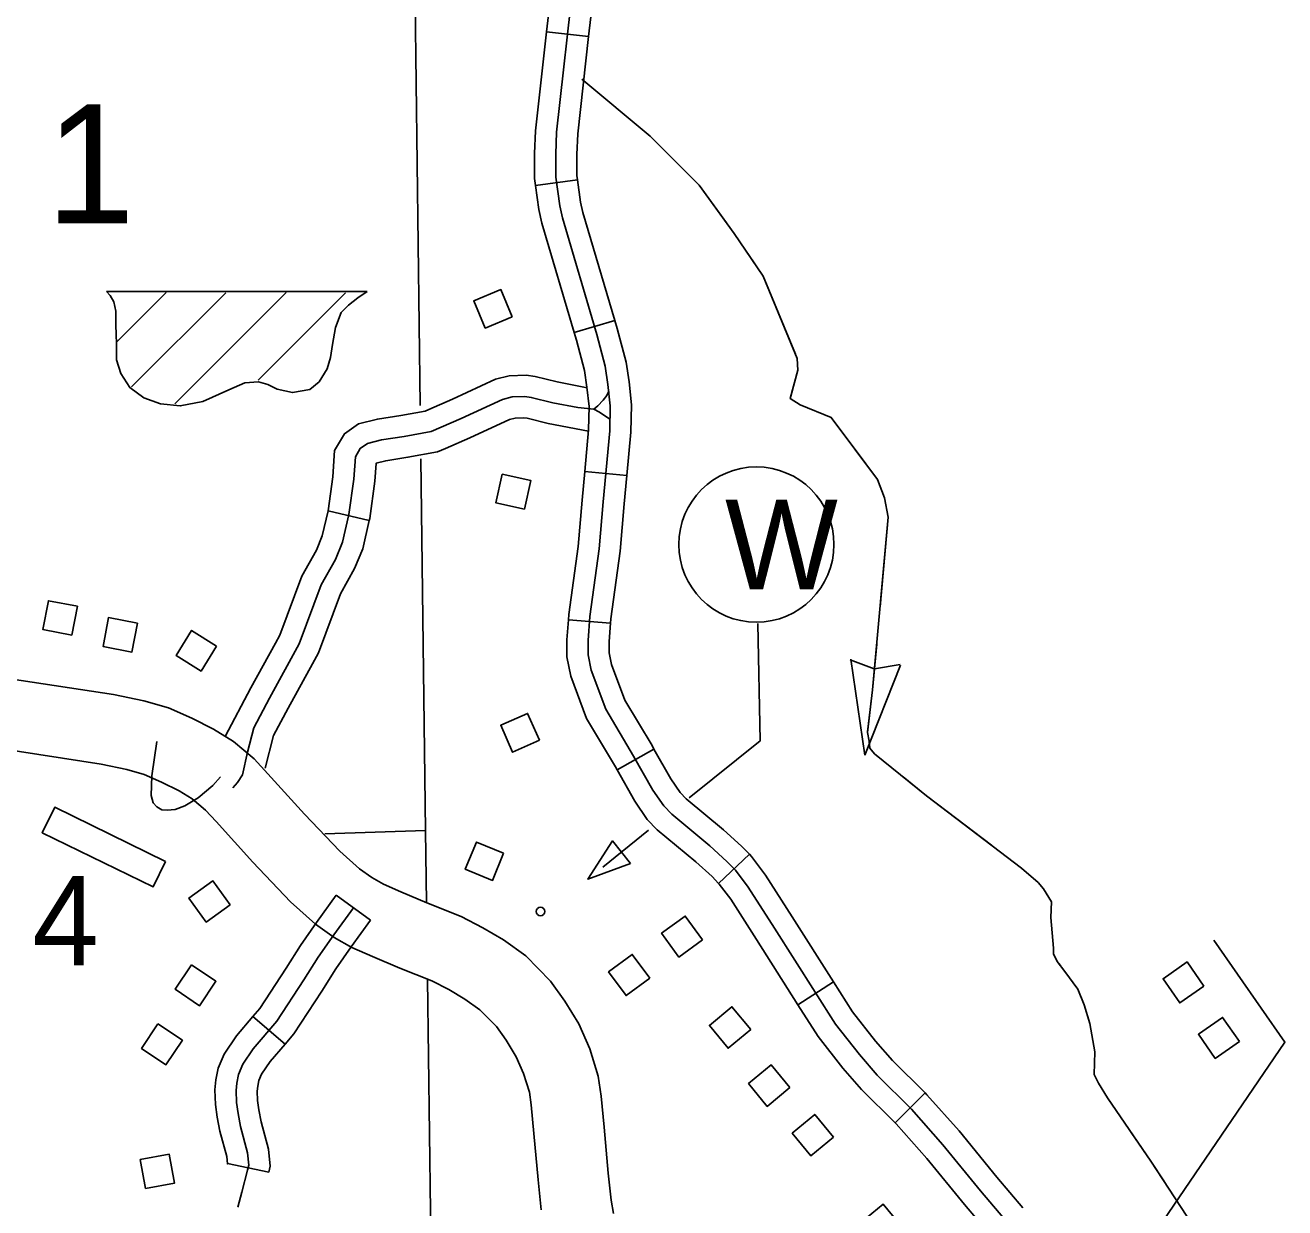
# Model space of a CAD drawing. Extents: x 155 to 3386, y 68 to 2138.
# Drawn here: x 2032.7 to 2160.3, y 1017.8 to 1137.5 of the extents above; entities that cross this region are included whole.
import ezdxf

# ---------------------------------------------------------------- set-up
doc = ezdxf.new("R2010")
doc.units = 0
for name, color, linetype in [('Level 10', 7, 'Continuous'), ('Level 32', 7, 'Continuous'), ('Level 43', 7, 'Continuous'), ('Level 45', 7, 'Continuous'), ('Level 5', 7, 'Continuous'), ('Level 56', 7, 'Continuous'), ('Level 57', 7, 'Continuous')]:
    doc.layers.add(name, color=color, linetype=linetype)

msp = doc.modelspace()

# ---------------------------------------------------------------- linework, layer by layer
at = {"layer": 'Level 10'}
for points in [[(2092.33, 1017.22), (2092.09, 1018.57), (2091.8, 1021.3), (2091.38, 1025.93), (2091.09, 1029.09), (2090.78, 1031.1), (2089.92, 1033.88), (2088.82, 1036.39), (2087.41, 1038.69), (2085.96, 1040.73), (2083.44, 1043.29), (2081.17, 1044.9), (2079.09, 1046.12), (2076.9, 1047.26), (2073.43, 1048.64), (2070.78, 1049.78), (2069.03, 1050.56), (2067.85, 1051.21), (2066.59, 1052.1), (2064.6, 1053.88), (2061.04, 1057.65), (2057.33, 1061.72), (2055.92, 1063.24), (2053.85, 1064.98), (2051.82, 1066.23), (2049.62, 1067.34), (2047.24, 1068.4), (2044.74, 1069.11), (2041.69, 1069.74), (2031.2, 1071.34)], [(2030.21, 1064.27), (2040.43, 1062.7), (2043.04, 1062.17), (2044.8, 1061.66), (2046.56, 1060.89), (2048.32, 1059.99), (2049.65, 1059.17), (2050.99, 1058.05), (2052.08, 1056.88), (2055.8, 1052.79), (2059.61, 1048.75), (2062.13, 1046.51), (2064.04, 1045.15), (2065.84, 1044.15), (2067.93, 1043.23), (2070.7, 1042.04), (2073.93, 1040.75), (2075.64, 1039.87), (2077.28, 1038.9), (2078.79, 1037.83), (2080.47, 1036.12), (2081.45, 1034.74), (2082.48, 1033.08), (2083.21, 1031.39), (2083.81, 1029.48), (2084, 1028.22), (2084.27, 1025.29), (2084.69, 1020.6), (2085.01, 1017.58)]]:
    msp.add_lwpolyline(points, dxfattribs=at)
at = {"layer": 'Level 32'}
for p, q in [((2085.55, 1136.83), (2089.81, 1136.36)), ((2084.43, 1121.28), (2088.68, 1121.87)), ((2088.36, 1106.41), (2092.47, 1107.63)), ((2089.41, 1092.33), (2093.68, 1091.93)), ((2087.76, 1077.3), (2092.03, 1076.98)), ((2092.69, 1062.12), (2096.42, 1064.23)), ((2102.98, 1050.62), (2106.09, 1053.57)), ((2064.25, 1049.42), (2067.71, 1046.89)), ((2111.01, 1038.34), (2114.62, 1040.65)), ((2055.81, 1037.14), (2059.06, 1034.35)), ((2120.87, 1026.37), (2123.89, 1029.42)), ((2053.22, 1022.25), (2057.42, 1021.39))]:
    msp.add_line(p, q, dxfattribs=at)
for points in [[(2087.62, 1151.32), (2087.24, 1149.53), (2086.24, 1142.92), (2085.55, 1136.83)], [(2091.95, 1151.07), (2091.46, 1148.77), (2090.49, 1142.36), (2089.81, 1136.36)], [(2088.36, 1142.64), (2086.57, 1126.67), (2086.48, 1124.47), (2086.48, 1122.14), (2086.88, 1119.22), (2087.15, 1118.01), (2090.65, 1106.21), (2091.5, 1102.98), (2091.77, 1101.14), (2092, 1098.98), (2091.95, 1096.43), (2091.28, 1089.25), (2090.87, 1084.49), (2089.93, 1077.63), (2089.75, 1075.2), (2089.75, 1073.77), (2090.07, 1072.2), (2091.55, 1068.25), (2094.37, 1063.49), (2096.3, 1060.08), (2097.42, 1058.47), (2098.23, 1057.62), (2102.07, 1054.42), (2103.82, 1052.85), (2104.67, 1051.95), (2105.97, 1050.25), (2108.62, 1046.08), (2114.8, 1036.38), (2117.23, 1033.29), (2119.02, 1031.22), (2122.52, 1027.76), (2125.7, 1024.17), (2129.51, 1019.5), (2134.22, 1013.94)], [(2085.55, 1136.83), (2084.43, 1126.83), (2084.34, 1124.51), (2084.34, 1121.99), (2084.43, 1121.28)], [(2089.81, 1136.36), (2088.71, 1126.5), (2088.62, 1124.43), (2088.62, 1122.28), (2088.68, 1121.87)], [(2088.68, 1121.87), (2088.99, 1119.6), (2089.23, 1118.55), (2092.47, 1107.63)], [(2084.43, 1121.28), (2084.77, 1118.84), (2085.08, 1117.47), (2088.36, 1106.41)], [(2092.47, 1107.63), (2092.71, 1106.79), (2093.61, 1103.41), (2093.9, 1101.4), (2094.14, 1099.08), (2094.09, 1096.31), (2093.68, 1091.93)], [(2088.36, 1106.41), (2088.59, 1105.63), (2089.4, 1102.55), (2089.64, 1100.87), (2089.85, 1098.89), (2089.81, 1096.55), (2089.41, 1092.33)], [(2089.41, 1092.33), (2089.14, 1089.44), (2088.74, 1084.73), (2087.8, 1077.85), (2087.76, 1077.3)], [(2093.68, 1091.93), (2093.41, 1089.06), (2093.01, 1084.26), (2092.06, 1077.4), (2092.03, 1076.98)], [(2087.76, 1077.3), (2087.61, 1075.28), (2087.61, 1073.56), (2088, 1071.61), (2089.61, 1067.32), (2092.52, 1062.42), (2092.69, 1062.12)], [(2092.03, 1076.98), (2091.9, 1075.13), (2091.9, 1073.98), (2092.13, 1072.79), (2093.49, 1069.18), (2096.23, 1064.57), (2096.42, 1064.23)], [(2046.08, 1065), (2045.56, 1061.53), (2045.49, 1059.53), (2045.7, 1058.79), (2046.06, 1058.36), (2046.59, 1058.07), (2047.12, 1058.04), (2047.94, 1058.11), (2048.9, 1058.47), (2050.26, 1059.28), (2051.75, 1060.53), (2052.53, 1061.42)], [(2096.42, 1064.23), (2098.12, 1061.22), (2099.09, 1059.82), (2099.7, 1059.18), (2103.47, 1056.04), (2105.31, 1054.39), (2106.09, 1053.57)], [(2092.69, 1062.12), (2094.48, 1058.94), (2095.75, 1057.11), (2096.76, 1056.05), (2100.67, 1052.8), (2102.32, 1051.31), (2102.98, 1050.62)], [(2106.09, 1053.57), (2106.3, 1053.35), (2107.73, 1051.47), (2110.42, 1047.23), (2114.62, 1040.65)], [(2102.98, 1050.62), (2103.04, 1050.56), (2104.21, 1049.02), (2106.81, 1044.93), (2111.01, 1038.34)], [(2064.25, 1049.42), (2062.24, 1046.67), (2060.64, 1044.33), (2059.17, 1042.03), (2056.51, 1037.96), (2055.81, 1037.14)], [(2065.98, 1048.16), (2063.99, 1045.43), (2062.43, 1043.15), (2060.97, 1040.87), (2058.23, 1036.67), (2055.84, 1033.89), (2054.77, 1032.33), (2054.35, 1031.29), (2054.17, 1030.4), (2054.1, 1029.65), (2054.13, 1028.44), (2054.31, 1027.34), (2054.56, 1026.02), (2055.27, 1023.35), (2055.38, 1022.11), (2055.27, 1021.59), (2054.67, 1019.38), (2054.28, 1017.85)], [(2067.71, 1046.89), (2065.74, 1044.19), (2064.21, 1041.97), (2062.77, 1039.71), (2059.94, 1035.38), (2059.06, 1034.35)], [(2114.62, 1040.65), (2116.55, 1037.62), (2118.88, 1034.65), (2120.58, 1032.69), (2123.89, 1029.42)], [(2111.01, 1038.34), (2113.05, 1035.14), (2115.57, 1031.92), (2117.45, 1029.76), (2120.87, 1026.37)], [(2055.81, 1037.14), (2054.14, 1035.2), (2052.88, 1033.35), (2052.29, 1031.92), (2052.05, 1030.72), (2051.95, 1029.73), (2052, 1028.24), (2052.2, 1026.97), (2052.47, 1025.55), (2053.15, 1022.98), (2053.22, 1022.23), (2053.22, 1022.25)], [(2059.06, 1034.35), (2057.55, 1032.59), (2056.67, 1031.3), (2056.41, 1030.67), (2056.29, 1030.09), (2056.24, 1029.58), (2056.27, 1028.65), (2056.42, 1027.71), (2056.65, 1026.5), (2057.39, 1023.72), (2057.54, 1021.98), (2057.42, 1021.39)], [(2123.89, 1029.42), (2124.07, 1029.23), (2127.33, 1025.56), (2131.16, 1020.87), (2133.78, 1017.78)], [(2120.87, 1026.37), (2120.96, 1026.28), (2124.07, 1022.78), (2127.87, 1018.13), (2130.5, 1015.01)]]:
    msp.add_lwpolyline(points, dxfattribs=at)
at = {"layer": 'Level 43'}
for p, q in [((2116.29, 1073.25), (2118.74, 1072.35)), ((2117.79, 1063.61), (2116.37, 1073.31)), ((2117.79, 1063.61), (2121.41, 1072.72)), ((2121.35, 1072.79), (2118.78, 1072.35))]:
    msp.add_line(p, q, dxfattribs=at)
for points in [[(2089.13, 1132.04), (2096.03, 1126.28), (2101, 1121.32), (2104.54, 1116.42), (2107.49, 1112.1), (2110.94, 1103.75), (2111.01, 1102.6), (2110.22, 1099.72), (2111.23, 1099.08), (2114.39, 1097.78), (2119.07, 1091.52), (2119.79, 1089.65), (2120.15, 1087.7), (2118.56, 1070.21), (2118.06, 1065.89), (2118.21, 1065.03), (2118.28, 1064.31), (2118.78, 1063.73), (2124.03, 1059.49), (2133.67, 1052.15), (2135.33, 1050.71), (2135.9, 1050.06), (2136.69, 1048.76), (2136.62, 1047.18), (2136.91, 1044.08), (2136.91, 1043.51), (2137.27, 1042.72), (2138.06, 1041.71), (2139.36, 1039.91), (2140, 1038.33), (2140.58, 1036.45), (2141.08, 1033.57), (2141.01, 1031.27), (2141.44, 1030.41), (2142.38, 1028.9), (2146.77, 1022.49), (2150.4, 1016.95)], [(2096.34, 1125.97), (2101, 1121.32), (2103.77, 1117.49)], [(2105.92, 1114.39), (2107.49, 1112.1), (2110.75, 1104.21)], [(2110.45, 1100.55), (2110.22, 1099.72), (2111.23, 1099.08), (2114.39, 1097.78), (2117.88, 1093.1)], [(2119.71, 1089.84), (2119.79, 1089.65), (2120.15, 1087.7), (2119.33, 1078.61)], [(2118.99, 1074.86), (2118.56, 1070.21), (2118.07, 1065.96)], [(2121.66, 1061.4), (2124.03, 1059.49), (2126.11, 1057.91)], [(2126.11, 1057.91), (2130.61, 1054.48)], [(2133.61, 1052.19), (2133.67, 1052.15), (2135.33, 1050.71), (2135.9, 1050.06), (2136.69, 1048.76), (2136.62, 1047.18), (2136.91, 1044.08), (2136.91, 1043.51), (2137.27, 1042.72), (2137.59, 1042.31)], [(2139.66, 1039.18), (2140, 1038.33), (2140.58, 1036.45), (2141.08, 1033.57), (2141.01, 1031.27), (2141.44, 1030.41), (2142.38, 1028.9), (2142.64, 1028.51)], [(2144.77, 1025.4), (2146.77, 1022.49), (2148.13, 1020.42)]]:
    msp.add_lwpolyline(points, dxfattribs=at)
at = {"layer": 'Level 45'}
msp.add_line((2067.59, 1087.37), (2063.42, 1088.34), dxfattribs=at)
for points in [[(2073.61, 1098.61), (2076.02, 1099.64), (2080.36, 1101.66), (2081.77, 1102), (2083.47, 1102.07), (2084.4, 1101.94), (2086.63, 1101.39), (2089.65, 1100.81)], [(2053.77, 1060.3), (2054.23, 1060.83), (2054.74, 1061.62), (2055.24, 1063.92), (2055.89, 1066.37), (2057.47, 1069.39), (2060.49, 1074.87), (2062.72, 1080.84), (2064.16, 1083.43), (2064.88, 1085.16), (2065.53, 1087.97), (2066.03, 1091.56), (2066.18, 1093.8), (2066.68, 1094.66), (2067.4, 1095.16), (2068.84, 1095.52), (2071.14, 1095.88), (2073.87, 1096.39), (2076.9, 1097.68), (2081.07, 1099.63), (2082.07, 1099.87), (2083.36, 1099.92), (2083.99, 1099.83), (2086.17, 1099.29), (2088.7, 1098.81), (2090.32, 1098.65)], [(2091.97, 1097.62), (2090.92, 1098.34), (2090.32, 1098.65), (2090.74, 1098.97), (2091.28, 1099.55), (2091.65, 1100.03), (2091.84, 1100.46)], [(2063.42, 1088.34), (2063.42, 1088.36), (2063.9, 1091.78), (2064.07, 1094.44), (2065.07, 1096.14), (2066.49, 1097.15), (2068.41, 1097.63), (2070.78, 1098), (2073.25, 1098.45), (2073.61, 1098.61)], [(2075.3, 1094.67), (2077.77, 1095.73), (2081.78, 1097.59), (2082.37, 1097.74), (2083.25, 1097.77), (2083.58, 1097.73), (2085.71, 1097.2), (2089.8, 1096.42)], [(2067.59, 1087.37), (2067.64, 1087.58), (2068.17, 1091.35), (2068.28, 1093.15), (2068.29, 1093.17), (2068.3, 1093.18), (2069.26, 1093.42), (2071.5, 1093.77), (2074.5, 1094.32), (2075.3, 1094.67)], [(2058.08, 1074.93), (2058.54, 1075.76), (2060.77, 1081.74), (2062.23, 1084.37), (2062.83, 1085.82), (2063.42, 1088.34)], [(2061.83, 1072.86), (2062.44, 1073.97), (2064.67, 1079.94), (2066.09, 1082.5), (2066.93, 1084.5), (2067.59, 1087.37)], [(2053.01, 1065.49), (2055.58, 1070.41), (2058.08, 1074.93)], [(2057.03, 1062.3), (2057.9, 1065.59), (2059.36, 1068.38), (2061.83, 1072.86)]]:
    msp.add_lwpolyline(points, dxfattribs=at)
at = {"layer": 'Level 5'}
for points in [[(2072.13, 1148.03), (2072.75, 1099.02)], [(2072.82, 1093.62), (2073.29, 1055.99)], [(2063.08, 1055.65), (2073.29, 1055.99)], [(2073.29, 1055.99), (2073.39, 1048.66)], [(2073.49, 1040.92), (2073.91, 1009.62)]]:
    msp.add_lwpolyline(points, dxfattribs=at)
at = {"layer": 'Level 56'}
for points in [[(2082.07, 1107.99), (2079.33, 1106.85), (2078.18, 1109.6), (2080.93, 1110.74)], [(2081.04, 1092.07), (2083.95, 1091.43), (2083.3, 1088.52), (2080.4, 1089.16)], [(2038.02, 1078.68), (2037.46, 1075.76), (2034.53, 1076.32), (2035.09, 1079.24)], [(2044.1, 1076.97), (2043.55, 1074.05), (2040.62, 1074.61), (2041.17, 1077.53)], [(2052.12, 1074.64), (2050.55, 1072.12), (2048.02, 1073.7), (2049.6, 1076.23)], [(2084.83, 1065.11), (2082.11, 1063.9), (2080.91, 1066.63), (2083.63, 1067.83)], [(2046.96, 1052.84), (2045.7, 1050.27), (2034.47, 1055.76), (2035.73, 1058.33)], [(2081.2, 1053.68), (2080.08, 1050.93), (2077.32, 1052.06), (2078.44, 1054.81)], [(2053.49, 1048.44), (2051.07, 1046.71), (2049.33, 1049.14), (2051.75, 1050.87)], [(2101.36, 1044.92), (2098.96, 1043.16), (2097.2, 1045.57), (2099.6, 1047.32)], [(2096, 1041.02), (2093.6, 1039.27), (2091.83, 1041.67), (2094.23, 1043.43)], [(2152.14, 1040.22), (2149.69, 1038.52), (2147.99, 1040.97), (2150.43, 1042.67)], [(2049.59, 1042.38), (2052.06, 1040.72), (2050.4, 1038.24), (2047.93, 1039.9)], [(2106.23, 1035.84), (2103.94, 1033.94), (2102.04, 1036.24), (2104.33, 1038.14)], [(2046.19, 1036.39), (2048.66, 1034.74), (2047, 1032.26), (2044.53, 1033.92)], [(2155.72, 1034.61), (2153.28, 1032.91), (2151.58, 1035.36), (2154.02, 1037.06)], [(2110.2, 1029.95), (2107.91, 1028.05), (2106.01, 1030.35), (2108.3, 1032.25)], [(2114.62, 1024.93), (2112.33, 1023.04), (2110.43, 1025.33), (2112.72, 1027.23)], [(2044.94, 1019.74), (2044.4, 1022.67), (2047.33, 1023.21), (2047.87, 1020.29)], [(2121.53, 1015.87), (2119.24, 1013.97), (2117.34, 1016.26), (2119.63, 1018.16)]]:
    msp.add_lwpolyline(points, close=True, dxfattribs=at)
msp.add_lwpolyline([(2146.42, 1014.12), (2160.33, 1034.54), (2153.15, 1044.86)], dxfattribs=at)
at = {"layer": 'Level 57'}
for p, q in [((2040.97, 1110.55), (2067.37, 1110.55)), ((2042.05, 1105.48), (2047.02, 1110.45)), ((2043.52, 1100.89), (2053.05, 1110.41)), ((2047.88, 1099.18), (2059.16, 1110.46)), ((2056.33, 1101.57), (2065.17, 1110.41))]:
    msp.add_line(p, q, dxfattribs=at)
for points in [[(2040.97, 1110.55), (2041.34, 1110.13), (2041.7, 1109.5), (2041.93, 1108.56), (2041.93, 1107.14), (2041.97, 1105.28), (2041.97, 1103.63), (2042.44, 1102.25), (2043.35, 1100.83), (2044.77, 1099.8), (2046.43, 1099.17), (2048.44, 1098.97), (2050.73, 1099.41), (2053.37, 1100.59), (2054.99, 1101.3), (2056.37, 1101.42), (2057.31, 1101.14), (2058.26, 1100.67), (2059.8, 1100.31), (2061.57, 1100.63), (2062.52, 1101.42), (2063.31, 1102.72), (2063.66, 1103.86), (2063.86, 1105.2), (2064.18, 1106.9), (2064.73, 1108.44), (2065.48, 1109.15), (2066.43, 1109.9), (2067.37, 1110.55)], [(2106.95, 1076.95), (2107.17, 1065.05), (2099.98, 1059.28)], [(2095.89, 1056), (2091.25, 1052.26)]]:
    msp.add_lwpolyline(points, dxfattribs=at)
msp.add_lwpolyline([(2094.06, 1052.65), (2092.24, 1054.92), (2089.74, 1051.05)], close=True, dxfattribs=at)
for centre, radius in [((2106.8, 1084.93), 7.86), ((2084.94, 1047.78), 0.429)]:
    msp.add_circle(centre, radius, dxfattribs=at)

# ---------------------------------------------------------------- texts
at = {"layer": 'Level 5'}
msp.add_text('1', height=12.07, dxfattribs=at).set_placement((2034.85, 1117.44))
at = {"layer": 'Level 56'}
msp.add_text('4', height=9.05, dxfattribs=at).set_placement((2033.47, 1042.34))
at = {"layer": 'Level 57'}
msp.add_text('W', height=9.05, dxfattribs=at).set_placement((2103.63, 1080.41))

doc.saveas('drawing.dxf')
